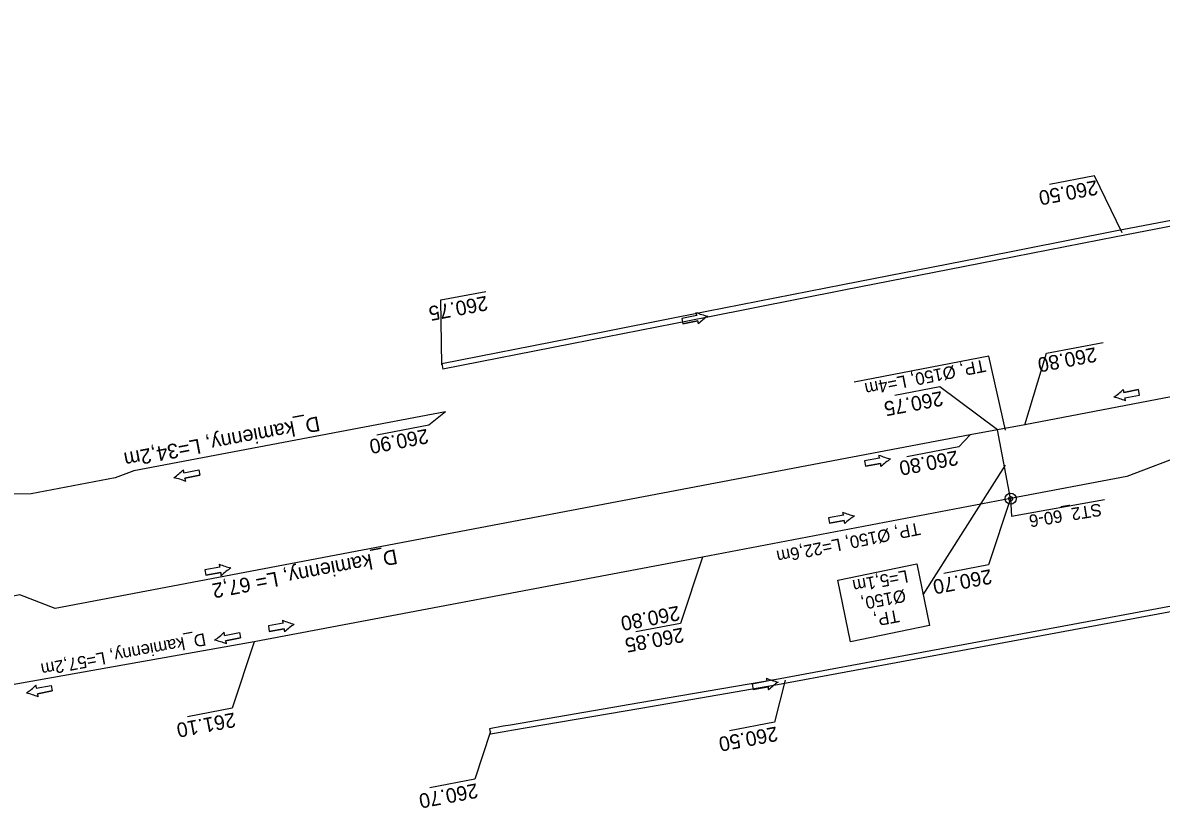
# Model space of a CAD drawing. Extents: x -1 to 65640748, y -22 to 5530284.
# Drawn here: x 6558626.1 to 6558708.2, y 5528885.6 to 5528942.3 of the extents above; entities that cross this region are included whole.
import ezdxf

# ---------------------------------------------------------------- set-up
doc = ezdxf.new("R2010")
doc.units = 0
for name, color, linetype in [('TOR_PS_ODW-drenaze', 7, 'Continuous'), ('TOR_PS_ODW-drenokolektory', 7, 'Continuous'), ('TOR_PS_ODW-studnie PEHD', 7, 'Continuous'), ('TOR_PS_OPIS_O-opisy rurociagow', 7, 'Continuous'), ('TOR_PS_OPIS_O-opisy studni', 7, 'Continuous'), ('TOR_PS_OPIS_T-INFO', 7, 'Continuous'), ('TOR_PS_T-rowy otwarte umocnione', 7, 'Continuous')]:
    doc.layers.add(name, color=color, linetype=linetype)

msp = doc.modelspace()

# ---------------------------------------------------------------- linework, layer by layer
at = {"layer": 'TOR_PS_ODW-drenaze'}
for p, q in [((6558773.925, 5528927.61), (6558698.366, 5528913.287)), ((6558698.366, 5528913.287), (6558694.436, 5528912.542)), ((6558694.436, 5528912.542), (6558628.457, 5528900.036)), ((6558697.342, 5528907.953), (6558696.401, 5528912.915)), ((6558697.342, 5528907.953), (6558675.134, 5528903.744))]:
    msp.add_line(p, q, dxfattribs=at)
for points in [[(6558656.587, 5528914.223), (6558634.137, 5528909.967), (6558632.791, 5528909.458), (6558626.727, 5528908.308), (6558622.984, 5528908.26)], [(6558675.134, 5528903.744), (6558642.81, 5528897.617), (6558618.841, 5528893.385)]]:
    msp.add_lwpolyline(points, dxfattribs=at)
at = {"layer": 'TOR_PS_ODW-drenokolektory'}
msp.add_lwpolyline([(6558756.292, 5528919.127), (6558721.8, 5528912.589), (6558717.193, 5528912.53), (6558710.034, 5528911.173), (6558705.725, 5528909.542), (6558705.725, 5528909.542), (6558697.342, 5528907.953)], dxfattribs=at)
at = {"layer": 'TOR_PS_ODW-studnie PEHD'}
for radius in [0.4, 0.145]:
    msp.add_circle((6558697.342, 5528907.953), radius, dxfattribs=at)
at = {"layer": 'TOR_PS_OPIS_O-opisy rurociagow'}
for p, q in [((6558674.712, 5528921.165), (6558673.64, 5528920.952)), ((6558674.712, 5528921.165), (6558673.64, 5528920.952)), ((6558674.712, 5528921.165), (6558673.64, 5528920.952)), ((6558674.712, 5528921.165), (6558673.64, 5528920.952)), ((6558673.64, 5528920.952), (6558673.718, 5528920.559)), ((6558673.64, 5528920.952), (6558673.718, 5528920.559)), ((6558673.64, 5528920.952), (6558673.718, 5528920.559)), ((6558673.64, 5528920.952), (6558673.718, 5528920.559)), ((6558673.718, 5528920.559), (6558674.79, 5528920.773)), ((6558674.79, 5528920.773), (6558673.718, 5528920.559)), ((6558673.718, 5528920.559), (6558674.79, 5528920.773)), ((6558674.79, 5528920.773), (6558673.718, 5528920.559)), ((6558706.572, 5528915.815), (6558705.498, 5528915.612)), ((6558705.498, 5528915.612), (6558706.572, 5528915.815)), ((6558706.647, 5528915.422), (6558706.572, 5528915.815)), ((6558706.647, 5528915.422), (6558706.572, 5528915.815)), ((6558705.573, 5528915.219), (6558706.647, 5528915.422)), ((6558705.573, 5528915.219), (6558706.647, 5528915.422)), ((6558687.89, 5528910.878), (6558686.815, 5528910.687)), ((6558687.89, 5528910.878), (6558686.815, 5528910.687)), ((6558637.732, 5528909.811), (6558638.803, 5528910.026)), ((6558637.732, 5528909.811), (6558638.803, 5528910.026)), ((6558638.803, 5528910.026), (6558638.882, 5528909.634)), ((6558638.803, 5528910.026), (6558638.882, 5528909.634)), ((6558686.815, 5528910.687), (6558686.885, 5528910.293)), ((6558686.815, 5528910.687), (6558686.885, 5528910.293)), ((6558686.885, 5528910.293), (6558687.96, 5528910.484)), ((6558687.96, 5528910.484), (6558686.885, 5528910.293)), ((6558638.882, 5528909.634), (6558637.811, 5528909.419)), ((6558637.811, 5528909.419), (6558638.882, 5528909.634)), ((6558685.282, 5528906.765), (6558684.206, 5528906.574)), ((6558685.282, 5528906.765), (6558684.206, 5528906.574)), ((6558684.206, 5528906.574), (6558684.276, 5528906.18)), ((6558684.206, 5528906.574), (6558684.276, 5528906.18)), ((6558684.276, 5528906.18), (6558685.352, 5528906.372)), ((6558685.352, 5528906.372), (6558684.276, 5528906.18)), ((6558640.33, 5528903.015), (6558639.254, 5528902.824)), ((6558640.33, 5528903.015), (6558639.254, 5528902.824)), ((6558639.254, 5528902.824), (6558639.324, 5528902.43)), ((6558639.254, 5528902.824), (6558639.324, 5528902.43)), ((6558639.324, 5528902.43), (6558640.4, 5528902.622)), ((6558640.4, 5528902.622), (6558639.324, 5528902.43)), ((6558644.901, 5528898.964), (6558643.825, 5528898.772)), ((6558644.901, 5528898.964), (6558643.825, 5528898.772)), ((6558643.825, 5528898.772), (6558643.895, 5528898.378)), ((6558643.825, 5528898.772), (6558643.895, 5528898.378)), ((6558643.895, 5528898.378), (6558644.971, 5528898.57)), ((6558644.971, 5528898.57), (6558643.895, 5528898.378)), ((6558640.666, 5528898.092), (6558641.737, 5528898.307)), ((6558640.666, 5528898.092), (6558641.737, 5528898.307)), ((6558641.816, 5528897.915), (6558640.744, 5528897.7)), ((6558640.744, 5528897.7), (6558641.816, 5528897.915)), ((6558641.737, 5528898.307), (6558641.816, 5528897.915)), ((6558641.737, 5528898.307), (6558641.816, 5528897.915)), ((6558627.096, 5528894.276), (6558628.168, 5528894.491)), ((6558627.096, 5528894.276), (6558628.168, 5528894.491)), ((6558628.168, 5528894.491), (6558628.246, 5528894.099)), ((6558628.168, 5528894.491), (6558628.246, 5528894.099)), ((6558679.786, 5528894.783), (6558678.712, 5528894.583)), ((6558679.786, 5528894.783), (6558678.712, 5528894.583)), ((6558679.786, 5528894.783), (6558678.712, 5528894.583)), ((6558679.786, 5528894.783), (6558678.712, 5528894.583)), ((6558678.712, 5528894.583), (6558678.785, 5528894.19)), ((6558678.712, 5528894.583), (6558678.785, 5528894.19)), ((6558678.712, 5528894.583), (6558678.785, 5528894.19)), ((6558678.712, 5528894.583), (6558678.785, 5528894.19)), ((6558679.788, 5528894.783), (6558678.714, 5528894.584)), ((6558679.788, 5528894.783), (6558678.714, 5528894.584)), ((6558678.714, 5528894.584), (6558678.787, 5528894.19)), ((6558678.714, 5528894.584), (6558678.787, 5528894.19)), ((6558678.785, 5528894.19), (6558679.859, 5528894.39)), ((6558679.859, 5528894.39), (6558678.785, 5528894.19)), ((6558678.785, 5528894.19), (6558679.859, 5528894.39)), ((6558679.859, 5528894.39), (6558678.785, 5528894.19)), ((6558678.787, 5528894.19), (6558679.861, 5528894.39)), ((6558679.861, 5528894.39), (6558678.787, 5528894.19)), ((6558628.246, 5528894.099), (6558627.175, 5528893.884)), ((6558627.175, 5528893.884), (6558628.246, 5528894.099))]:
    msp.add_line(p, q, dxfattribs=at)
for points in [[(6558674.658, 5528921.383), (6558674.658, 5528921.383)], [(6558674.658, 5528921.383), (6558674.658, 5528921.383)], [(6558674.824, 5528920.55), (6558674.824, 5528920.55)], [(6558674.824, 5528920.55), (6558674.824, 5528920.55)], [(6558705.467, 5528915.834), (6558705.467, 5528915.834)], [(6558705.625, 5528915), (6558705.625, 5528915)], [(6558687.841, 5528911.098), (6558687.841, 5528911.098)], [(6558637.698, 5528910.033), (6558637.698, 5528910.033)], [(6558687.99, 5528910.261), (6558687.99, 5528910.261)], [(6558637.865, 5528909.2), (6558637.865, 5528909.2)], [(6558685.232, 5528906.985), (6558685.232, 5528906.985)], [(6558685.381, 5528906.148), (6558685.381, 5528906.148)], [(6558640.28, 5528903.235), (6558640.28, 5528903.235)], [(6558640.429, 5528902.398), (6558640.429, 5528902.398)], [(6558644.851, 5528899.183), (6558644.851, 5528899.183)], [(6558640.631, 5528898.314), (6558640.631, 5528898.314)], [(6558645, 5528898.347), (6558645, 5528898.347)], [(6558640.799, 5528897.481), (6558640.799, 5528897.481)], [(6558627.062, 5528894.498), (6558627.062, 5528894.498)], [(6558679.735, 5528895.002), (6558679.735, 5528895.002)], [(6558679.735, 5528895.002), (6558679.735, 5528895.002)], [(6558679.737, 5528895.002), (6558679.737, 5528895.002)], [(6558627.23, 5528893.665), (6558627.23, 5528893.665)], [(6558679.89, 5528894.167), (6558679.89, 5528894.167)], [(6558679.89, 5528894.167), (6558679.89, 5528894.167)], [(6558679.892, 5528894.167), (6558679.892, 5528894.167)]]:
    msp.add_lwpolyline(points, dxfattribs=at)
for centre, radius, start, end in [((6558676.536, 5528925.928), 4.918, 247.54615, 257.92797), ((6558675.115, 5528921.381), 0.458, 179.66071, 208.12195), ((6558676.536, 5528925.928), 4.918, 247.54615, 257.92797), ((6558675.115, 5528921.381), 0.458, 179.66071, 208.12195), ((6558676.536, 5528925.928), 4.918, 247.54615, 257.92797), ((6558675.115, 5528921.381), 0.458, 179.66071, 208.12195), ((6558676.536, 5528925.928), 4.918, 247.54615, 257.92797), ((6558675.115, 5528921.381), 0.458, 179.66071, 208.12195), ((6558675.245, 5528920.728), 0.458, 174.39006, 202.8513), ((6558675.245, 5528920.728), 0.458, 174.39006, 202.8513), ((6558675.245, 5528920.728), 0.458, 174.39006, 202.8513), ((6558675.245, 5528920.728), 0.458, 174.39006, 202.8513), ((6558678.299, 5528917.071), 4.918, 124.58404, 134.96586), ((6558678.299, 5528917.071), 4.918, 124.58404, 134.96586), ((6558678.299, 5528917.071), 4.918, 124.58404, 134.96586), ((6558678.299, 5528917.071), 4.918, 124.58404, 134.96586), ((6558702.023, 5528919.345), 4.918, 304.06127, 314.4431), ((6558702.023, 5528919.345), 4.918, 304.06127, 314.4431), ((6558705.043, 5528915.66), 0.458, 353.86729, 22.32853), ((6558705.043, 5528915.66), 0.458, 353.86729, 22.32853), ((6558703.705, 5528910.472), 4.918, 67.02338, 77.40521), ((6558703.705, 5528910.472), 4.918, 67.02338, 77.40521), ((6558705.167, 5528915.006), 0.458, 359.13794, 27.59919), ((6558705.167, 5528915.006), 0.458, 359.13794, 27.59919), ((6558689.811, 5528915.604), 4.918, 246.38098, 256.76281), ((6558688.298, 5528911.086), 0.458, 178.49555, 206.95679), ((6558689.811, 5528915.604), 4.918, 246.38098, 256.76281), ((6558688.298, 5528911.086), 0.458, 178.49555, 206.95679), ((6558691.394, 5528906.712), 4.918, 123.41887, 133.8007), ((6558691.394, 5528906.712), 4.918, 123.41887, 133.8007), ((6558634.215, 5528913.505), 4.918, 304.70367, 315.0855), ((6558634.215, 5528913.505), 4.918, 304.70367, 315.0855), ((6558637.276, 5528909.855), 0.458, 354.50969, 22.97093), ((6558637.276, 5528909.855), 0.458, 354.50969, 22.97093), ((6558688.415, 5528910.43), 0.458, 173.22489, 201.68613), ((6558688.415, 5528910.43), 0.458, 173.22489, 201.68613), ((6558635.997, 5528904.651), 4.918, 67.66578, 78.04761), ((6558635.997, 5528904.651), 4.918, 67.66578, 78.04761), ((6558637.408, 5528909.202), 0.458, 359.78034, 28.24158), ((6558637.408, 5528909.202), 0.458, 359.78034, 28.24158), ((6558687.203, 5528911.491), 4.918, 246.38098, 256.76281), ((6558685.69, 5528906.973), 0.458, 178.49555, 206.95679), ((6558687.203, 5528911.491), 4.918, 246.38098, 256.76281), ((6558685.69, 5528906.973), 0.458, 178.49555, 206.95679), ((6558688.785, 5528902.599), 4.918, 123.41887, 133.8007), ((6558688.785, 5528902.599), 4.918, 123.41887, 133.8007), ((6558685.806, 5528906.318), 0.458, 173.22489, 201.68613), ((6558685.806, 5528906.318), 0.458, 173.22489, 201.68613), ((6558642.25, 5528907.741), 4.918, 246.38098, 256.76281), ((6558640.738, 5528903.223), 0.458, 178.49555, 206.95679), ((6558642.25, 5528907.741), 4.918, 246.38098, 256.76281), ((6558640.738, 5528903.223), 0.458, 178.49555, 206.95679), ((6558640.854, 5528902.568), 0.458, 173.22489, 201.68613), ((6558640.854, 5528902.568), 0.458, 173.22489, 201.68613), ((6558643.833, 5528898.849), 4.918, 123.41887, 133.8007), ((6558643.833, 5528898.849), 4.918, 123.41887, 133.8007), ((6558646.821, 5528903.689), 4.918, 246.38098, 256.76281), ((6558645.309, 5528899.171), 0.458, 178.49555, 206.95679), ((6558646.821, 5528903.689), 4.918, 246.38098, 256.76281), ((6558645.309, 5528899.171), 0.458, 178.49555, 206.95679), ((6558645.425, 5528898.516), 0.458, 173.22489, 201.68613), ((6558645.425, 5528898.516), 0.458, 173.22489, 201.68613), ((6558648.404, 5528894.797), 4.918, 123.41887, 133.8007), ((6558648.404, 5528894.797), 4.918, 123.41887, 133.8007), ((6558637.149, 5528901.787), 4.918, 304.70367, 315.0855), ((6558637.149, 5528901.787), 4.918, 304.70367, 315.0855), ((6558638.93, 5528892.932), 4.918, 67.66578, 78.04761), ((6558638.93, 5528892.932), 4.918, 67.66578, 78.04761), ((6558640.21, 5528898.136), 0.458, 354.50969, 22.97093), ((6558640.21, 5528898.136), 0.458, 354.50969, 22.97093), ((6558640.341, 5528897.483), 0.458, 359.78034, 28.24158), ((6558640.341, 5528897.483), 0.458, 359.78034, 28.24158), ((6558623.58, 5528897.971), 4.918, 304.70367, 315.0855), ((6558623.58, 5528897.971), 4.918, 304.70367, 315.0855), ((6558626.641, 5528894.32), 0.458, 354.50969, 22.97093), ((6558626.641, 5528894.32), 0.458, 354.50969, 22.97093), ((6558681.671, 5528899.523), 4.918, 246.81126, 257.19308), ((6558680.193, 5528894.993), 0.458, 178.92582, 207.38706), ((6558681.671, 5528899.523), 4.918, 246.81126, 257.19308), ((6558680.193, 5528894.993), 0.458, 178.92582, 207.38706), ((6558681.671, 5528899.523), 4.918, 246.81126, 257.19308), ((6558680.193, 5528894.993), 0.458, 178.92582, 207.38706), ((6558681.671, 5528899.523), 4.918, 246.81126, 257.19308), ((6558680.193, 5528894.993), 0.458, 178.92582, 207.38706), ((6558681.673, 5528899.523), 4.918, 246.81126, 257.19308), ((6558680.195, 5528894.994), 0.458, 178.92582, 207.38706), ((6558681.673, 5528899.523), 4.918, 246.81126, 257.19308), ((6558680.195, 5528894.994), 0.458, 178.92582, 207.38706), ((6558680.314, 5528894.339), 0.458, 173.65517, 202.11641), ((6558680.314, 5528894.339), 0.458, 173.65517, 202.11641), ((6558680.314, 5528894.339), 0.458, 173.65517, 202.11641), ((6558680.314, 5528894.339), 0.458, 173.65517, 202.11641), ((6558680.316, 5528894.339), 0.458, 173.65517, 202.11641), ((6558680.316, 5528894.339), 0.458, 173.65517, 202.11641), ((6558683.321, 5528890.643), 4.918, 123.84914, 134.23097), ((6558683.321, 5528890.643), 4.918, 123.84914, 134.23097), ((6558683.321, 5528890.643), 4.918, 123.84914, 134.23097), ((6558683.321, 5528890.643), 4.918, 123.84914, 134.23097), ((6558683.322, 5528890.643), 4.918, 123.84914, 134.23097), ((6558683.322, 5528890.643), 4.918, 123.84914, 134.23097), ((6558625.361, 5528889.116), 4.918, 67.66578, 78.04761), ((6558625.361, 5528889.116), 4.918, 67.66578, 78.04761), ((6558626.772, 5528893.667), 0.458, 359.78034, 28.24158), ((6558626.772, 5528893.667), 0.458, 359.78034, 28.24158)]:
    msp.add_arc(centre, radius, start, end, dxfattribs=at)
at = {"layer": 'TOR_PS_OPIS_T-INFO'}
msp.add_line((6558691.041, 5528901.028), (6558696.976, 5528910.362), dxfattribs=at)
for points in [[(6558705.391, 5528927.117), (6558703.389, 5528931.218), (6558700.155, 5528930.594)], [(6558656.322, 5528917.596), (6558656.258, 5528922.284), (6558659.495, 5528922.887)], [(6558698.366, 5528913.287), (6558699.922, 5528918.437), (6558704.022, 5528919.2)], [(6558696.972, 5528912.892), (6558695.77, 5528918.221), (6558686.068, 5528916.349)], [(6558696.401, 5528912.915), (6558692.231, 5528916.008), (6558688.998, 5528915.384)], [(6558656.587, 5528914.223), (6558655.4, 5528913.243), (6558651.657, 5528912.521)], [(6558694.436, 5528912.542), (6558693.599, 5528911.681), (6558689.856, 5528910.959)], [(6558697.342, 5528907.953), (6558695.759, 5528903.17), (6558692.525, 5528902.546)], [(6558697.342, 5528907.953), (6558697.411, 5528906.689), (6558704.109, 5528907.887)], [(6558675.134, 5528903.744), (6558673.55, 5528898.96), (6558670.317, 5528898.337)], [(6558628.457, 5528900.036), (6558625.915, 5528901.014), (6558622.172, 5528900.292)], [(6558642.81, 5528897.617), (6558641.227, 5528892.833), (6558637.994, 5528892.21)], [(6558681.093, 5528894.858), (6558680.317, 5528891.827), (6558677.084, 5528891.203)], [(6558659.836, 5528891.157), (6558658.702, 5528887.73), (6558655.468, 5528887.106)]]:
    msp.add_lwpolyline(points, dxfattribs=at)
msp.add_lwpolyline([(6558691.499, 5528898.804), (6558685.81, 5528897.634), (6558684.895, 5528902.08), (6558690.583, 5528903.251)], close=True, dxfattribs=at)
at = {"layer": 'TOR_PS_T-rowy otwarte umocnione'}
for points in [[(6558783.453, 5528942.267), (6558773.631, 5528940.388), (6558763.809, 5528938.51), (6558753.987, 5528936.631), (6558744.165, 5528934.753), (6558734.343, 5528932.874), (6558724.521, 5528930.995), (6558714.699, 5528929.117), (6558704.878, 5528927.235), (6558695.066, 5528925.303), (6558685.254, 5528923.371), (6558675.442, 5528921.439), (6558665.63, 5528919.507), (6558656.34, 5528917.678), (6558656.415, 5528917.285)], [(6558783.528, 5528941.874), (6558773.706, 5528939.995), (6558763.884, 5528938.117), (6558754.062, 5528936.238), (6558744.24, 5528934.36), (6558734.418, 5528932.481), (6558724.596, 5528930.602), (6558714.774, 5528928.724), (6558704.952, 5528926.842), (6558695.14, 5528924.91), (6558685.329, 5528922.978), (6558675.517, 5528921.046), (6558665.705, 5528919.114), (6558656.415, 5528917.285)], [(6558788.643, 5528914.885), (6558778.786, 5528913.192), (6558768.955, 5528911.363), (6558759.123, 5528909.535), (6558749.292, 5528907.707), (6558739.46, 5528905.878), (6558729.629, 5528904.05), (6558719.797, 5528902.222), (6558709.966, 5528900.393), (6558700.134, 5528898.565), (6558690.303, 5528896.737), (6558680.47, 5528894.913), (6558670.613, 5528893.224), (6558661.279, 5528891.624), (6558660.755, 5528891.535), (6558659.769, 5528891.366), (6558659.843, 5528890.973)], [(6558788.718, 5528914.492), (6558778.861, 5528912.799), (6558769.029, 5528910.97), (6558759.198, 5528909.142), (6558749.366, 5528907.314), (6558739.535, 5528905.485), (6558729.703, 5528903.657), (6558719.872, 5528901.829), (6558710.04, 5528900), (6558700.209, 5528898.172), (6558690.377, 5528896.344), (6558680.545, 5528894.52), (6558670.687, 5528892.831), (6558661.353, 5528891.231), (6558660.829, 5528891.142), (6558659.843, 5528890.973)]]:
    msp.add_lwpolyline(points, dxfattribs=at)

# ---------------------------------------------------------------- texts
at = {"layer": 'TOR_PS_OPIS_O-opisy rurociagow'}
for s, height, rotation, p in [('TP, Ø150, L=4m', 0.9, 191.29864, (6558695.443, 5528918.001)), ('D_kamienny, L=34,2m', 1.06875, 190.67544, (6558647.427, 5528913.901)), ('TP, Ø150, L=22,6m', 0.9, 191.29864, (6558690.728, 5528906.238)), ('D_kamienny, L= 67,2', 1.06875, 190.67544, (6558653.011, 5528904.314)), ('L=5,1m', 0.9, 190.68392, (6558689.855, 5528902.815)), ('Ø150, ', 0.9, 190.68392, (6558689.695, 5528901.411)), ('TP, ', 0.9, 190.68392, (6558689.224, 5528899.949)), ('D_kamienny, L=57,2m', 0.9, 190.59848, (6558639.226, 5528898.264))]:
    msp.add_text(s, height=height, rotation=rotation, dxfattribs=at).set_placement(p)
at = {"layer": 'TOR_PS_OPIS_O-opisy studni'}
msp.add_text('ST2_60-6', height=0.9, rotation=189.34322, dxfattribs=at).set_placement((6558703.831, 5528907.62))
at = {"layer": 'TOR_PS_OPIS_T-INFO'}
for s, rotation, p in [('260.50', 190.71587, (6558703.52, 5528930.922)), ('260.75', 190.75061, (6558659.537, 5528922.586)), ('260.80', 190.71587, (6558703.442, 5528918.877)), ('260.75', 190.71587, (6558692.365, 5528915.713)), ('260.90', 190.71587, (6558655.26, 5528912.996)), ('260.80', 190.71587, (6558693.459, 5528911.434)), ('260.70', 190.71587, (6558695.89, 5528902.874)), ('260.80', 190.71587, (6558673.384, 5528900.236)), ('260.85', 190.71587, (6558673.684, 5528898.665)), ('261.10', 190.71587, (6558641.358, 5528892.538)), ('260.50', 190.71587, (6558680.448, 5528891.532)), ('260.70', 190.71587, (6558658.833, 5528887.434))]:
    msp.add_text(s, height=1.05, rotation=rotation, dxfattribs=at).set_placement(p)

doc.saveas('drawing.dxf')
